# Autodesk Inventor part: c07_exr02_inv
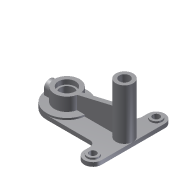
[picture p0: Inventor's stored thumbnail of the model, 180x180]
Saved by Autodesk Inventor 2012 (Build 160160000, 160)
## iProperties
Shininess: 77.0
Length Units: 11269
Angle Units: 11279
Time Units: 11290
Mass Units: 11283
Length Display Precision: 3
Angle Display Precision: 2
Created: 2001-12
Part Number: c07_exr02_inv
Document SubType Name: Modeling
Density: 1 g/cm^3
Material: Default
Density: 0.0
Volumn: 0.0
Area: 0.0
PropertySet Name: Model Information
Control State: 0
Master: False
Checked Out: False
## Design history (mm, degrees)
sketch "Sketch1"
  geometry: L1 (46.121, -53.4)-(46.121, 56.6); L2 (16.121, 56.6)-(16.121, 36.6); L3 (16.121, 36.6)-(-68.879, 36.6); L4 (-68.879, -33.4)-(16.121, -33.4); L5 (16.121, -33.4)-(16.121, -53.4); A1 r 15 centre (31.121, 56.6) between (46.121, 56.6) and (16.121, 56.6); A2 r 35 centre (-68.879, 1.6) between (-68.879, 36.6) and (-68.879, -33.4); A3 r 15 centre (31.121, -53.4) between (16.121, -53.4) and (46.121, -53.4)
  constraints: 10 end point, 6 point on circle, 5 tangent, 3 centre point, 3 parallel, 2 equal length, 1 equal radius, 1 perpendicular, 1 vertical
  dimensions: "d0" = 15 radius of A1; "d1" = 110 distance of L1.start L1.end; "d2" = 100 horizontal distance of A3.centre A2.centre; "d3" = 35 radius of A2
extrude "Extrusion1" new body sketch "Sketch1" distance "d4" = 7; taper "d5" = 0 deg
sketch "Sketch2"
  geometry: C1 r 10 at (31.121, 56.6); C2 r 10 at (31.121, -53.4); C3 r 35 at (-68.879, 1.6); A1 r 35 centre (-68.879, 1.6) between (-68.879, 36.6) and (-68.879, -33.4) reference; A2 r 15 centre (31.121, 56.6) between (46.121, 56.6) and (16.121, 56.6) reference; A3 r 15 centre (31.121, -53.4) between (16.121, -53.4) and (46.121, -53.4) reference
  constraints: 3 centre point, 3 concentric, 2 equal radius
  dimensions: "d45" = 20 diameter of C1
extrude "Extrusion2" join sketch "Sketch2" distance "d6" = 3; taper "d7" = 0 deg
sketch "Sketch3"
  geometry: C1 r 22 at (0, 0); 1 further point
  constraints: 1 centre point, 1 coincident
  dimensions: "d8" = 44 diameter of C1
extrude "Extrusion3" join sketch "Sketch3" distance "d9" = 23; taper "d10" = 0 deg
sketch "Sketch4"
  geometry: L1 (46.121, 56.6)-(46.121, -53.4) reference; L2 (-68.879, 36.6)-(16.121, 36.6) reference; C1 r 15 at (31.121, 1.6)
  constraints: 1 centre point
  dimensions: "d11" = 30 diameter of C1; "d12" = 15 distance from line of L1 C1.centre; "d13" = 35 distance from line of L2 C1.centre
extrude "Extrusion4" join sketch "Sketch4" distance "d14" = 88; taper "d15" = 0 deg
workplane "Work Plane1"
sketch "Sketch5"
  geometry: L1 (22, 33.1)-(85, 48); L2 (0, 7)-(35, 7) reference; L3 (85, 0)-(85, 7) reference; L4 (115, 0)-(115, 7) reference; L5 (115, 0)-(85, 0) reference
  constraints: 2 end point
  dimensions: "d17" = 26.1 distance from line of L2 L1.start; "d18" = 63 distance from line of L3 L1.start; "d19" = 30 distance from line of L4 L1.end; "d20" = 48 distance from line of L5 L1.end
feature "Rib1" sketch "Sketch5" dims "d21" = 1, "d22" = 8
workplane "Work Plane2"
workplane "Work Plane3"
sketch "Sketch7"
  geometry: L1 (10, 0)-(10, 10); L2 (-10, 10)-(-10, 0); L3 (-10, 0)-(10, 0); L4 (55, -10)-(55, -3) reference; A1 r 10 centre (0, 10) between (10, 10) and (-10, 10); 2 further points
  constraints: 6 end point, 2 point on circle, 2 tangent, 1 centre point, 1 parallel, 1 perpendicular, 1 vertical
  dimensions: "d30" = 10 radius of A1; "d34" = 55 distance from line of L4 A1.centre; "d35" = 10 distance of L1.start L1.end
extrude "Extrusion6" join sketch "Sketch7" stored distance "d36" = 88; taper "d37" = 0 deg
sketch "Sketch8"
  geometry: C1 r 10 at (0, 0) reference
hole "Hole1" sketch "Sketch8" at (0, 0) diameter "d38" = 12; stored, may be unused: countersink angle "d42" = 82 deg, drill point angle "d44" = 118 deg; dims "d39" = 6, "d40" = 4, "d41" = 2, "d43" = 8
mirror "Mirror1"
sketch "Sketch9"
  geometry: C1 r 10 at (0, 0)
  constraints: 1 centre point
hole "Hole2" sketch "Sketch9" at (0, 0) diameter "d52" = 18; stored, may be unused: drill point angle "d47" = 118 deg, countersink angle "d48" = 82 deg; dims "d46" = 6, "d49" = 2, "d50" = 4, "d51" = 8
sketch "Sketch10"
  geometry: C1 r 10 at (0, 0)
  constraints: 1 centre point
hole "Hole3" sketch "Sketch10" at (0, 0) diameter "d59" = 24; stored, may be unused: drill point angle "d54" = 118 deg, countersink angle "d55" = 82 deg; dims "d53" = 6, "d56" = 8, "d57" = 30, "d58" = 8
sketch "Sketch11"
  geometry: C1 r 10 at (0, 0)
  constraints: 1 centre point
hole "Hole4" sketch "Sketch11" at (0, 0) diameter "d66" = 10; stored, may be unused: drill point angle "d61" = 0 deg, countersink angle "d62" = 82 deg; dims "d60" = 6, "d63" = 2, "d64" = 4, "d65" = 8
fillet "Fillet1" dims "d67" = 10
body "Solid1"
other parameters: "d16" = -35, "d29" = -8
